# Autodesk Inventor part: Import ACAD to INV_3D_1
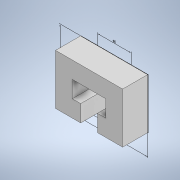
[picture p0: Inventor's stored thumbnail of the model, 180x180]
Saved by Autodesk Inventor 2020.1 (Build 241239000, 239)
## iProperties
Created: 2019-11
Part Number: Import ACAD to INV_3D_1
Material: Generic
Document SubType Name: Modeling
Designer: Synergysoft Dell02
Density: 1 g/cm^3
Appearance: Default
Author: Synergysoft Dell02
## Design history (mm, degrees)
node "Import ACAD to INV_1.dwg"
sketch "Sketch1"
  geometry: L1 (80, 0)-(80, 60) reference; L2 (50, 0)-(80, 0) reference; L3 (50, 20)-(50, 0) reference; L4 (60, 20)-(50, 20) reference; L5 (60, 40)-(60, 20) reference; L6 (20, 40)-(60, 40) reference; L7 (20, 20)-(20, 40) reference; L8 (30, 20)-(20, 20) reference; L9 (30, 0)-(30, 20) reference; L10 (0, 0)-(30, 0) reference; L11 (0, 60)-(0, 0) reference; L12 (80, 60)-(0, 60) reference
extrude "Extrusion1" new body sketch "Sketch1" distance "d0" = 30; taper "d1" = 0 deg
body "Solid1"
